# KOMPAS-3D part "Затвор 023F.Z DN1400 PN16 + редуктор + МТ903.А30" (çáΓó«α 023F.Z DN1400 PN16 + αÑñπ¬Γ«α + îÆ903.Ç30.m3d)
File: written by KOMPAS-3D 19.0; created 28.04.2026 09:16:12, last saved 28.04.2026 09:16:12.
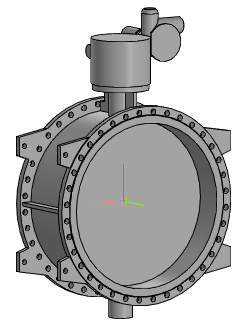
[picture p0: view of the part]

Document properties: Автор: Энергия; Полное имя файла: ..\..\Затвор 023F.Z DN400-DN1600 + редуктор + МТ903\Затвор 023F.Z DN1400 PN16 + редуктор + МТ903.А30.a3d

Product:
- Part/product: Затвор 023F.Z DN1400 PN16 + редуктор + МТ903.А30
    Масса: 3724.23

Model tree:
1. Операция без истории:1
